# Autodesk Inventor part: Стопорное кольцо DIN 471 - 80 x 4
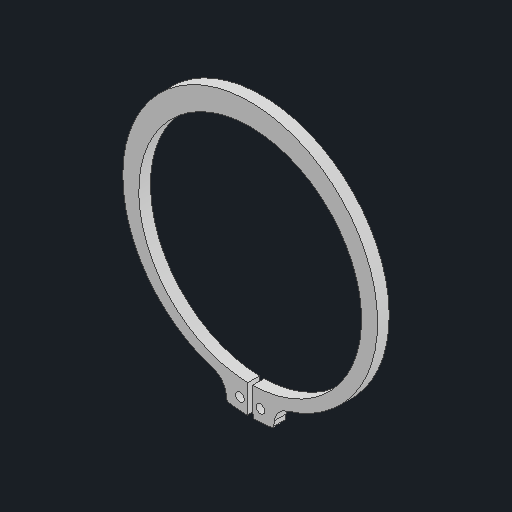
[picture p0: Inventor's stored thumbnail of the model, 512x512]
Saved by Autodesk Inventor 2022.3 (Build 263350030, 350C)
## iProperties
Created: 2020-09
Part Number: Стопорное кольцо DIN 471 - 80 x 4
Material: Типовые
Description: Стопортное кольцо DIN 471 - 80 x 4
Document SubType Name: Modeling
Designer: Карташов
Density: 1 g/cm^3
Appearance: По умолчанию
Title: D:\мои документы\Ирина\_WorldSkills\2020_09 ФНЧ\Module A\Участникам\GIVEN\Стопорное кольцо DIN 471 - 80 x 4.stp
Author: Дом
Sending System: Autodesk Inventor 2021
Preprocessor: ST-DEVELOPER v18.1
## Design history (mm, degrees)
feature "Твердое тело2"
node "Твердое тело1"
